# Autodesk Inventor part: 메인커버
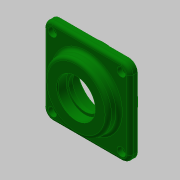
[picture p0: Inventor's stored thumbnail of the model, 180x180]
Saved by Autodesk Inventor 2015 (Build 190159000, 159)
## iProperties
Created: 2018-09
Part Number: 메인커버
Material: 일반
Document SubType Name: Modeling
Designer: mduedu
Density: 1 g/cm^3
Appearance: 진녹색
Mass: 65.8536 g
Surface Area: 197.883 cm^2
Volume: 65.8536 cm^3
Author: mduedu
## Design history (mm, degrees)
sketch "스케치1"
  geometry: L1 (-40, -40)-(40, -40); L2 (40, -40)-(40, 40); L3 (40, 40)-(-40, 40); L4 (-40, 40)-(-40, -40); L5 (-40, -40)-(40, 40); L6 (40, -40)-(-40, 40); 1 further point
  constraints: 12 end point, 2 midpoint, 2 parallel, 1 horizontal, 1 perpendicular
  dimensions: "d0" = 80 distance of L3.end L2.end; "d1" = 80 distance of L2.end L1.end
extrude "돌출1" new body sketch "스케치1" distance "d2" = 7; taper "d3" = 0 deg
sketch "스케치2"
  geometry: C1 r 30 at (0, 0); 1 further point
  constraints: 1 centre point, 1 coincident
  dimensions: "d4" = 60 diameter of C1
extrude "돌출2" join sketch "스케치2" distance "d5" = 10; taper "d6" = 0 deg
sketch "스케치3"
  geometry: C1 r 32.5 at (0, 0); 1 further point
  constraints: 1 centre point, 1 coincident
  dimensions: "d7" = 65 diameter of C1
extrude "돌출3" join sketch "스케치3" distance "d8" = 9; taper "d9" = 0 deg
sketch "스케치4"
  geometry: L1 (-32.5, -9)-(32.5, -9) reference; L2 (30, 17)-(-30, 17) reference; L3 (0, 17)-(0, -9); L4 (0, -9)-(23.5, -9); L5 (23.5, -9)-(23.5, 5); L6 (23.5, 5)-(0, 5); L7 (0, 5)-(0, -9); L8 (0, 5)-(15, 5); L9 (15, 5)-(15, 8.7); L10 (15, 8.7)-(0, 8.7); L11 (0, 8.7)-(0, 5); L12 (0, 8.7)-(17.5, 8.7); L13 (17.5, 8.7)-(17.5, 17); L14 (17.5, 17)-(0, 17); L15 (0, 17)-(0, 8.7); 1 further point
  constraints: 26 end point, 6 parallel, 3 horizontal, 3 perpendicular, 2 midpoint, 1 point on line
  dimensions: "d10" = 14 distance of L4.end L5.end; "d12" = 8.3 distance of L12.end L13.end; "d13" = 35 diameter of L13 L3; "d14" = 30 diameter of L9 L3; "d15" = 47 diameter of L5 L3
revolve "회전1" sketch "스케치4" stored, may be unused: angle "d16" = 90 deg
fillet "모깎기1" dims "d17" = 8
fillet "모깎기2" dims "d18" = 3
fillet "모깎기3" dims "d19" = 3
chamfer "모따기1" distance "d20" = 0.8; stored, may be unused: second distance "d21" = 2, angle "d22" = 30 deg
chamfer "모따기2" distance "d23" = 1; stored, may be unused: second distance "d24" = 2, angle "d25" = 30 deg
fillet "모깎기4" dims "d26" = 0.3
sketch "스케치5"
  geometry: A1 r 8 centre (-32, 32) between (-32, 40) and (-40, 32) reference; A2 r 8 centre (-32, -32) between (-40, -32) and (-32, -40) reference; A3 r 8 centre (32, -32) between (32, -40) and (40, -32) reference; A4 r 8 centre (32, 32) between (40, 32) and (32, 40) reference; 5 further points
  constraints: 4 coincident
hole "구멍1" sketch "스케치5" at (-32, 32), (32, 32), (32, -32), (-32, -32) diameter "d27" = 4.5; stored, may be unused: countersink angle "d31" = 90 deg, drill point angle "d33" = 118 deg; dims "d28" = 6, "d29" = 8, "d30" = 4.4, "d32" = 8
node "솔리드1"
